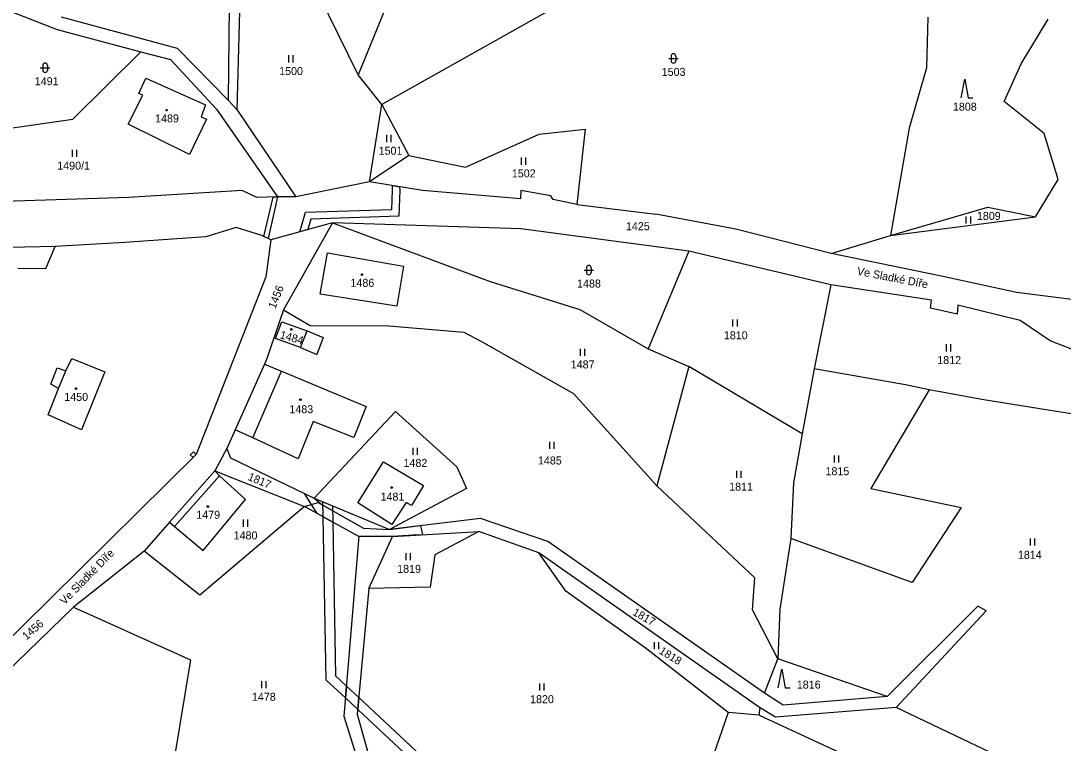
# Model space of a CAD drawing. Extents: x -670359 to -668019, y -978807 to -976674.
# Drawn here: x -669122.6 to -668901.2, y -978669.5 to -978516 of the extents above; entities that cross this region are included whole.
import ezdxf

# ---------------------------------------------------------------- set-up
doc = ezdxf.new("R2010")
doc.units = 0
for name, color, linetype in [('Hranice parcel', 7, 'Continuous'), ('Parcelní čísla', 7, 'Continuous'), ('Pop  PČ popisy', 7, 'Continuous'), ('Vnitřní kresba', 7, 'Continuous'), ('Věcná břemena k části', 7, 'Continuous'), ('Značky budov', 7, 'Continuous'), ('Značky kultur', 7, 'Continuous')]:
    doc.layers.add(name, color=color, linetype=linetype)

msp = doc.modelspace()

# ---------------------------------------------------------------- linework, layer by layer
at = {"layer": 'Hranice parcel'}
for points in [[(-669050.94, -978527.45), (-669069.9, -978488.77)], [(-669037.87, -978495.52), (-669050.94, -978527.45)], [(-669078.25, -978506.04), (-669078.53, -978532.83)], [(-669075.93, -978506.06), (-669076.71, -978534.85)], [(-669132.89, -978510.73), (-669114.87, -978517.8)], [(-669008.9, -978513.02), (-669045.91, -978533.73)], [(-669113.97, -978515.09), (-669089.38, -978521.76)], [(-668929.94, -978515.21), (-668930.2, -978525.93)], [(-668910.1, -978525.08), (-668904.33, -978515.58)], [(-669114.87, -978517.8), (-669097.05, -978522.55)], [(-669111.55, -978536.87), (-669097.05, -978522.55)], [(-669097.05, -978522.55), (-669090.77, -978524.22)], [(-669089.38, -978521.76), (-669078.53, -978532.83)], [(-669090.77, -978524.22), (-669081.03, -978534.72)], [(-668930.2, -978525.93), (-668933.87, -978538.82)], [(-668913.68, -978533.1), (-668910.1, -978525.08)], [(-669097.49, -978531.43), (-669096.01, -978528.16)], [(-669096.01, -978528.16), (-669083.35, -978533.82)], [(-669045.91, -978533.73), (-669050.94, -978527.45)], [(-669099.8, -978537.96), (-669096.69, -978531.75)], [(-669096.69, -978531.75), (-669097.49, -978531.43)], [(-669083.35, -978533.82), (-669084.29, -978536.41)], [(-669081.03, -978534.72), (-669068.02, -978553.42)], [(-669078.53, -978532.83), (-669076.71, -978534.85)], [(-669048.49, -978550.2), (-669045.91, -978533.73)], [(-669045.91, -978533.73), (-669040.18, -978544.63)], [(-668905.23, -978539.89), (-668913.68, -978533.1)], [(-669125.82, -978538.9), (-669111.55, -978536.87)], [(-669083.1, -978536.9), (-669086.74, -978544.38)], [(-669084.29, -978536.41), (-669083.1, -978536.9)], [(-669076.71, -978534.85), (-669064.18, -978553.38)], [(-669086.74, -978544.38), (-669099.8, -978537.96)], [(-669012.49, -978540.08), (-669002.7, -978538.97)], [(-669002.7, -978538.97), (-669004.5, -978555.02)], [(-668933.87, -978538.82), (-668937.86, -978561.63)], [(-669028.14, -978547.08), (-669012.49, -978540.08)], [(-668902.2, -978549.7), (-668905.23, -978539.89)], [(-669040.18, -978544.63), (-669048.49, -978550.2)], [(-669040.18, -978544.63), (-669028.14, -978547.08)], [(-669048.49, -978550.2), (-669064.18, -978553.38)], [(-669037.27, -978552.07), (-669048.49, -978550.2)], [(-668907.06, -978557.61), (-668902.2, -978549.7)], [(-669075.53, -978552.06), (-669099.72, -978553.56)], [(-669072.43, -978553.53), (-669075.53, -978552.06)], [(-669016.4, -978553.82), (-669037.27, -978552.07)], [(-669016.38, -978552.06), (-669016.4, -978553.82)], [(-669009.99, -978553.17), (-669016.38, -978552.06)], [(-669099.72, -978553.56), (-669137.18, -978554.7)], [(-669068.02, -978553.42), (-669072.43, -978553.53)], [(-669064.18, -978553.38), (-669068.02, -978553.42)], [(-669009.51, -978553.97), (-669009.99, -978553.17)], [(-669004.5, -978555.02), (-669009.51, -978553.97)], [(-669004.5, -978555.02), (-668987.68, -978557.05)], [(-668937.86, -978561.63), (-668917.19, -978555.59)], [(-668917.19, -978555.59), (-668907.06, -978557.61)], [(-669056.35, -978558.88), (-669069.48, -978562.52)], [(-669056.35, -978558.88), (-669066.76, -978577.43)], [(-669016.38, -978560.22), (-669056.35, -978558.88)], [(-669056.35, -978558.88), (-669022.91, -978571.42)], [(-668970.7, -978560.28), (-668987.68, -978557.05)], [(-668937.86, -978561.63), (-668907.06, -978557.61)], [(-669076.82, -978559.88), (-669083.24, -978561.89)], [(-669071.39, -978561.62), (-669076.82, -978559.88)], [(-668980.66, -978564.96), (-669016.38, -978560.22)], [(-668950.41, -978565.41), (-668970.7, -978560.28)], [(-669100.46, -978563.07), (-669115.28, -978563.95)], [(-669083.24, -978561.89), (-669100.46, -978563.07)], [(-669069.48, -978562.52), (-669071.39, -978561.62)], [(-669069.48, -978562.52), (-669070.52, -978570.43)], [(-668950.41, -978565.41), (-668937.86, -978561.63)], [(-669115.28, -978563.95), (-669124.89, -978564.16)], [(-669058.96, -978574.07), (-669057.42, -978565.29)], [(-669057.42, -978565.29), (-669041.28, -978568.11)], [(-668980.66, -978564.96), (-668989.34, -978585.68)], [(-668950.53, -978572.13), (-668980.66, -978564.96)], [(-668927.36, -978570.21), (-668950.41, -978565.41)], [(-669041.28, -978568.11), (-669042.73, -978576.65)], [(-668911.1, -978573.7), (-668927.36, -978570.21)], [(-669070.52, -978570.43), (-669085.33, -978608.18)], [(-669022.91, -978571.42), (-669003.84, -978577.31)], [(-668950.53, -978572.13), (-668954.08, -978589.98)], [(-668929.14, -978575.38), (-668950.53, -978572.13)], [(-669042.73, -978576.65), (-669058.96, -978574.07)], [(-668898.72, -978575.28), (-668911.1, -978573.7)], [(-668929.32, -978577.06), (-668929.14, -978575.38)], [(-668923.55, -978576.44), (-668923.66, -978578.36)], [(-668910.32, -978579.71), (-668923.55, -978576.44)], [(-669066.76, -978577.43), (-669070.39, -978587.95)], [(-669066.76, -978577.43), (-669061.11, -978580.77)], [(-669003.84, -978577.31), (-668989.34, -978585.68)], [(-668923.66, -978578.36), (-668929.32, -978577.06)], [(-669068.5, -978583.53), (-669067.1, -978579.94)], [(-669067.1, -978579.94), (-669061.76, -978581.88)], [(-669061.11, -978580.77), (-669044.38, -978580.79)], [(-669044.38, -978580.79), (-669028.46, -978582.16)], [(-668903.91, -978583.99), (-668910.32, -978579.71)], [(-669061.76, -978581.88), (-669058.34, -978583.31)], [(-669058.34, -978583.31), (-669059.69, -978586.9)], [(-669028.46, -978582.16), (-669024.72, -978584.12)], [(-669063.16, -978585.39), (-669068.5, -978583.53)], [(-669063.16, -978585.39), (-669059.69, -978586.9)], [(-669024.72, -978584.12), (-669005.15, -978595.21)], [(-668989.34, -978585.68), (-668980.68, -978589.43)], [(-668897.87, -978586.33), (-668903.91, -978583.99)], [(-669113, -978590.37), (-669111.77, -978587.74)], [(-669111.77, -978587.74), (-669104.76, -978590.62)], [(-669070.39, -978587.95), (-669070.84, -978588.96)], [(-669116.23, -978593.21), (-669114.83, -978589.71)], [(-669114.83, -978589.71), (-669113, -978590.37)], [(-669070.84, -978588.96), (-669077.06, -978602.9)], [(-669070.84, -978588.96), (-669067.21, -978590.46)], [(-668980.68, -978589.43), (-668987.45, -978614.83)], [(-668956.6, -978603.78), (-668980.68, -978589.43)], [(-668954.08, -978589.98), (-668956.6, -978603.78)], [(-668934.65, -978593.36), (-668954.08, -978589.98)], [(-669104.76, -978590.62), (-669109.69, -978602.96)], [(-669067.21, -978590.46), (-669049.2, -978597.93)], [(-669116.78, -978599.76), (-669114.56, -978594.11)], [(-669114.56, -978594.11), (-669116.23, -978593.21)], [(-668929.62, -978594.41), (-668941.99, -978615.39)], [(-668929.62, -978594.41), (-668934.65, -978593.36)], [(-668918.45, -978596.45), (-668929.62, -978594.41)], [(-669005.15, -978595.21), (-668987.45, -978614.83)], [(-668903.93, -978598.79), (-668918.45, -978596.45)], [(-669049.2, -978597.93), (-669051.83, -978604.54)], [(-668890.24, -978600.95), (-668903.93, -978598.79)], [(-669109.69, -978602.96), (-669116.78, -978599.76)], [(-669060.44, -978601.17), (-669063.65, -978609.06)], [(-669051.83, -978604.54), (-669060.44, -978601.17)], [(-669060.29, -978617.45), (-669042.97, -978599.04)], [(-669042.97, -978599.04), (-669029.94, -978610.79)], [(-669077.06, -978602.9), (-669078.83, -978606.89)], [(-669073.29, -978604.63), (-669077.06, -978602.9)], [(-669063.65, -978609.06), (-669073.29, -978604.63)], [(-668956.6, -978603.78), (-668958.46, -978614.22)], [(-669078.83, -978606.89), (-669081.37, -978611.66)], [(-669078.83, -978606.89), (-669078.05, -978608.9)], [(-669085.33, -978608.18), (-669147.05, -978669.18)], [(-669078.05, -978608.9), (-669060.29, -978617.45)], [(-669051.02, -978618.47), (-669045.56, -978609.73)], [(-669045.56, -978609.73), (-669037.05, -978614.78)], [(-669081.37, -978611.66), (-669090.98, -978622.57)], [(-669080.34, -978612.72), (-669081.37, -978611.66)], [(-669081.37, -978611.66), (-669062.31, -978619.23)], [(-669029.94, -978610.79), (-669027.88, -978615.4)], [(-669074.87, -978617.73), (-669080.34, -978612.72)], [(-668958.46, -978614.22), (-668958.99, -978626.05)], [(-669027.88, -978615.4), (-669044.28, -978624.09)], [(-669037.05, -978614.78), (-669039.58, -978618.99)], [(-668966.65, -978634.4), (-668987.45, -978614.83)], [(-668941.99, -978615.39), (-668922.85, -978619.41)], [(-669083.87, -978628.59), (-669074.87, -978617.73)], [(-669060.29, -978617.45), (-669044.28, -978624.09)], [(-669043.79, -978623.05), (-669051.02, -978618.47)], [(-669040.7, -978618.35), (-669043.79, -978623.05)], [(-669039.58, -978618.99), (-669040.7, -978618.35)], [(-669062.31, -978619.23), (-669084.53, -978638.1)], [(-669050.79, -978625.63), (-669062.31, -978619.23)], [(-668922.85, -978619.41), (-668933.21, -978635.39)], [(-669090.98, -978622.57), (-669096.38, -978628.7)], [(-669090.98, -978622.57), (-669089.9, -978623.49)], [(-669024.95, -978621.77), (-669044.28, -978624.09)], [(-669010.62, -978626.66), (-669024.95, -978621.77)], [(-669089.9, -978623.49), (-669083.87, -978628.59)], [(-669043.59, -978625.6), (-669025.31, -978624.56)], [(-669025.31, -978624.56), (-669034.6, -978629.52)], [(-669012.51, -978629.11), (-669025.31, -978624.56)], [(-669050.79, -978625.63), (-669053.93, -978663.82)], [(-669043.59, -978625.6), (-669050.79, -978625.63)], [(-669048.65, -978636.63), (-669043.59, -978625.6)], [(-668964.6, -978658.91), (-669010.62, -978626.66)], [(-668958.99, -978626.05), (-668961.37, -978641.07)], [(-668933.21, -978635.39), (-668958.99, -978626.05)], [(-669096.38, -978628.7), (-669111.37, -978640.61)], [(-669084.53, -978638.1), (-669096.38, -978628.7)], [(-669034.6, -978629.52), (-669035.6, -978636.38)], [(-668965.69, -978661.93), (-669012.51, -978629.11)], [(-669006.8, -978637.21), (-669012.51, -978629.11)], [(-668967.17, -978641.19), (-668966.65, -978634.4)], [(-669048.65, -978636.63), (-669051.12, -978663.39)], [(-669035.6, -978636.38), (-669048.65, -978636.63)], [(-668989.96, -978649.27), (-669006.8, -978637.21)], [(-669111.37, -978640.61), (-669155.12, -978683.09)], [(-669111.37, -978640.61), (-669086.51, -978651.84)], [(-668961.37, -978641.07), (-668961.75, -978651.6)], [(-668919.29, -978640.43), (-668938.52, -978659.61)], [(-668917.55, -978641.42), (-668919.29, -978640.43)], [(-668961.75, -978651.6), (-668967.17, -978641.19)], [(-668936.64, -978661.96), (-668917.55, -978641.42)], [(-668972.35, -978663.01), (-668989.96, -978649.27)], [(-669086.51, -978651.84), (-669089.85, -978672.04)], [(-668964.6, -978658.91), (-668961.75, -978651.6)], [(-668938.52, -978659.61), (-668961.75, -978651.6)], [(-668960.64, -978661.46), (-668964.6, -978658.91)], [(-668938.52, -978659.61), (-668960.64, -978661.46)], [(-668972.35, -978663.01), (-668976.23, -978674.31)], [(-668965.72, -978663.61), (-668972.35, -978663.01)], [(-668965.69, -978661.93), (-668965.72, -978663.61)], [(-668962.28, -978663.99), (-668965.69, -978661.93)], [(-668936.64, -978661.96), (-668962.28, -978663.99)], [(-668913.45, -978673.01), (-668936.64, -978661.96)], [(-669053.93, -978663.82), (-669050.36, -978675.32)], [(-669051.12, -978663.39), (-669047.95, -978674.8)], [(-668965.72, -978663.61), (-668944.52, -978673.42)]]:
    msp.add_lwpolyline(points, dxfattribs=at)
at = {"layer": 'Vnitřní kresba'}
for points in [[(-669117.25, -978568.65), (-669115.28, -978563.95)], [(-669123.18, -978568.58), (-669117.25, -978568.65)], [(-669063.16, -978585.39), (-669061.76, -978581.88)], [(-669114.56, -978594.11), (-669113, -978590.37)], [(-669073.29, -978604.63), (-669067.21, -978590.46)], [(-669089.9, -978623.49), (-669080.34, -978612.72)]]:
    msp.add_lwpolyline(points, dxfattribs=at)
at = {"layer": 'Věcná břemena k části'}
for p, q in [((-669070.96, -978561.82), (-669068.94, -978553.44)), ((-669068.02, -978553.42), (-669070.04, -978562.26)), ((-669068.94, -978553.44), (-669068.02, -978553.42))]:
    msp.add_line(p, q, dxfattribs=at)
for points in [[(-669061.59, -978560.33), (-669063.29, -978560.8), (-669062.1, -978556.66), (-669043.74, -978556.05), (-669043.6, -978551.98), (-669043.65, -978551.01), (-669042.14, -978551.26), (-669042.1, -978551.96), (-669042.3, -978557.51), (-669060.96, -978558.12), (-669061.59, -978560.33)], [(-669070.04, -978562.26), (-669070.96, -978561.82)], [(-669085.91, -978607.58), (-669085.33, -978608.18), (-669085.99, -978608.83), (-669086.58, -978608.23), (-669085.91, -978607.58)], [(-669062.35, -978616.46), (-669060.29, -978617.45), (-669058.56, -978618.86), (-669049.79, -978623.84), (-669044.28, -978624.09), (-669037.67, -978623.3), (-669037.22, -978625.24), (-669043.59, -978625.6), (-669050.79, -978625.63), (-669059.61, -978620.73), (-669062.35, -978616.46)], [(-669062.31, -978619.23), (-669059.42, -978618.36), (-669049.79, -978623.84), (-669044.28, -978624.09), (-669037.67, -978623.3), (-669037.22, -978625.24), (-669039.25, -978625.35), (-669043.59, -978625.6), (-669050.79, -978625.63), (-669056.33, -978622.55), (-669058.35, -978621.43), (-669059.61, -978620.73), (-669062.31, -978619.23)], [(-669058.35, -978621.43), (-669058.41, -978618.23), (-669056.4, -978619.06), (-669056.33, -978622.55), (-669058.35, -978621.43)], [(-669058.35, -978621.43), (-669056.33, -978622.55)], [(-669053.61, -978659.94), (-669057.69, -978656.12), (-669058.35, -978621.43)], [(-669056.33, -978622.55), (-669055.71, -978655.24)], [(-669055.71, -978655.24), (-669053.4, -978657.4)], [(-669053.4, -978657.4), (-669050.79, -978659.84), (-669051.02, -978662.36), (-669053.61, -978659.94), (-669053.4, -978657.4)], [(-669053.4, -978657.4), (-669053.61, -978659.94)], [(-669050.79, -978659.84), (-669024.44, -978684.5), (-669025.8, -978685.96), (-669051.02, -978662.36)], [(-669051.02, -978662.36), (-669050.79, -978659.84)]]:
    msp.add_lwpolyline(points, dxfattribs=at)
at = {"layer": 'Značky budov'}
for centre in [(-669091.59, -978534.96), (-669050.09, -978569.92), (-669065.11, -978581.58), (-669110.84, -978594.17), (-669063.18, -978596.5), (-669043.8, -978615.19), (-669082.84, -978619.23)]:
    msp.add_circle(centre, 0.175, dxfattribs=at)
at = {"layer": 'Značky kultur'}
for p, q in [((-669065.7, -978523.3), (-669065.7, -978524.8)), ((-669064.7, -978524.8), (-669064.7, -978523.3)), ((-668984.44, -978523.47), (-668984.44, -978524.47)), ((-668983.44, -978523.47), (-668983.44, -978524.47)), ((-669118.43, -978525.95), (-669116.43, -978525.95)), ((-669117.93, -978525.45), (-669117.93, -978526.45)), ((-669116.93, -978525.45), (-669116.93, -978526.45)), ((-668984.94, -978523.97), (-668982.94, -978523.97)), ((-669044.89, -978540.23), (-669044.89, -978541.73)), ((-669043.89, -978541.73), (-669043.89, -978540.23)), ((-669111.66, -978543.4), (-669111.66, -978544.9)), ((-669110.66, -978544.9), (-669110.66, -978543.4)), ((-669016.27, -978545.05), (-669016.27, -978546.55)), ((-669015.27, -978546.55), (-669015.27, -978545.05)), ((-668921.81, -978557.55), (-668921.81, -978559.05)), ((-668920.81, -978559.05), (-668920.81, -978557.55)), ((-669002.92, -978568.97), (-669000.92, -978568.97)), ((-669002.42, -978568.47), (-669002.42, -978569.47)), ((-669001.42, -978568.47), (-669001.42, -978569.47)), ((-668971.37, -978579.47), (-668971.37, -978580.97)), ((-668970.37, -978580.97), (-668970.37, -978579.47)), ((-669003.76, -978585.67), (-669003.76, -978587.17)), ((-669002.76, -978587.17), (-669002.76, -978585.67)), ((-668926.04, -978584.74), (-668926.04, -978586.24)), ((-668925.04, -978586.24), (-668925.04, -978584.74)), ((-669010.3, -978605.45), (-669010.3, -978606.95)), ((-669009.3, -978606.95), (-669009.3, -978605.45)), ((-669039.29, -978606.74), (-669039.29, -978608.24)), ((-669038.29, -978608.24), (-669038.29, -978606.74)), ((-668949.79, -978608.38), (-668949.79, -978609.88)), ((-668948.79, -978609.88), (-668948.79, -978608.38)), ((-668970.57, -978611.66), (-668970.57, -978613.16)), ((-668969.57, -978613.16), (-668969.57, -978611.66)), ((-669075.37, -978622.02), (-669075.37, -978623.52)), ((-669074.37, -978623.52), (-669074.37, -978622.02)), ((-668908.18, -978626), (-668908.18, -978627.5)), ((-668907.18, -978627.5), (-668907.18, -978626)), ((-669040.81, -978629.14), (-669040.81, -978630.64)), ((-669039.81, -978630.64), (-669039.81, -978629.14)), ((-668988.06, -978648.07), (-668988.06, -978649.57)), ((-668987.06, -978649.57), (-668987.06, -978648.07)), ((-669071.48, -978656.33), (-669071.48, -978657.83)), ((-669070.48, -978657.83), (-669070.48, -978656.33)), ((-669012.4, -978656.84), (-669012.4, -978658.34)), ((-669011.4, -978658.34), (-669011.4, -978656.84))]:
    msp.add_line(p, q, dxfattribs=at)
for points in [[(-668922.83, -978532.37), (-668922.08, -978528.37), (-668921.33, -978532.37), (-668920.33, -978532.37)], [(-668961.68, -978657.79), (-668960.93, -978653.79), (-668960.18, -978657.79), (-668959.18, -978657.79)]]:
    msp.add_lwpolyline(points, dxfattribs=at)
for centre in [(-669091.59, -978534.96), (-669050.09, -978569.92), (-669065.11, -978581.58), (-669110.84, -978594.17), (-669063.18, -978596.5), (-669043.8, -978615.19), (-669082.84, -978619.23)]:
    msp.add_circle(centre, 0.175, dxfattribs=at)
for centre, start, end in [((-668983.94, -978523.47), 0, 180), ((-669117.43, -978525.45), 0, 180), ((-668983.94, -978524.47), 180, 0), ((-669117.43, -978526.45), 180, 0), ((-669001.92, -978568.47), 0, 180), ((-669001.92, -978569.47), 180, 0)]:
    msp.add_arc(centre, 0.5, start, end, dxfattribs=at)

# ---------------------------------------------------------------- texts
at = {"layer": 'Parcelní čísla'}
for s, p in [('1500', (-669067.7, -978527.5)), ('1503', (-668986.44, -978527.67)), ('1491', (-669119.61, -978529.65)), ('1808', (-668924.58, -978535.07)), ('1489', (-669094.05, -978537.56)), ('1501', (-669046.57, -978544.43)), ('1490/1', (-669114.84, -978547.6)), ('1502', (-669018.27, -978549.25)), ('1809', (-668919.49, -978558.29)), ('1425', (-668994.04, -978560.48)), ('1486', (-669052.55, -978572.52)), ('1488', (-669004.42, -978572.67)), ('1810', (-668973.23, -978583.67)), ('1812', (-668927.9, -978588.94)), ('1487', (-669005.76, -978589.87)), ('1450', (-669113.34, -978596.77)), ('1483', (-669065.53, -978599.39)), ('1482', (-669041.29, -978610.81)), ('1485', (-669012.73, -978610.29)), ('1815', (-668951.65, -978612.58)), ('1811', (-668972.11, -978615.86)), ('1481', (-669046.16, -978617.99)), ('1479', (-669085.3, -978621.83)), ('1480', (-669077.37, -978626.22)), ('1814', (-668910.78, -978630.34)), ('1819', (-669042.63, -978633.34)), ('1816', (-668957.74, -978657.94)), ('1478', (-669073.48, -978660.53)), ('1820', (-669014.4, -978661.04))]:
    msp.add_text(s, height=1.7, dxfattribs=at).set_placement(p)
for s, rotation, p in [('1456', 68.5032, (-669068.52, -978577.32)), ('1484', 344.2192, (-669067.68, -978583.43)), ('1817', 337.249, (-669074.5, -978613.52)), ('1817', 330.3956, (-668992.79, -978642.18)), ('1456', 40.8503, (-669121.39, -978647.71)), ('1818', 328.2665, (-668987.16, -978650.35))]:
    msp.add_text(s, height=1.7, rotation=rotation, dxfattribs=at).set_placement(p)
at = {"layer": 'Pop  PČ popisy'}
for rotation, p in [(348.8975, (-668945.06, -978569.92)), (45.7649, (-669113.26, -978640.24))]:
    msp.add_text('Ve Sladké Díře', height=1.7, rotation=rotation, dxfattribs=at).set_placement(p)

doc.saveas('drawing.dxf')
